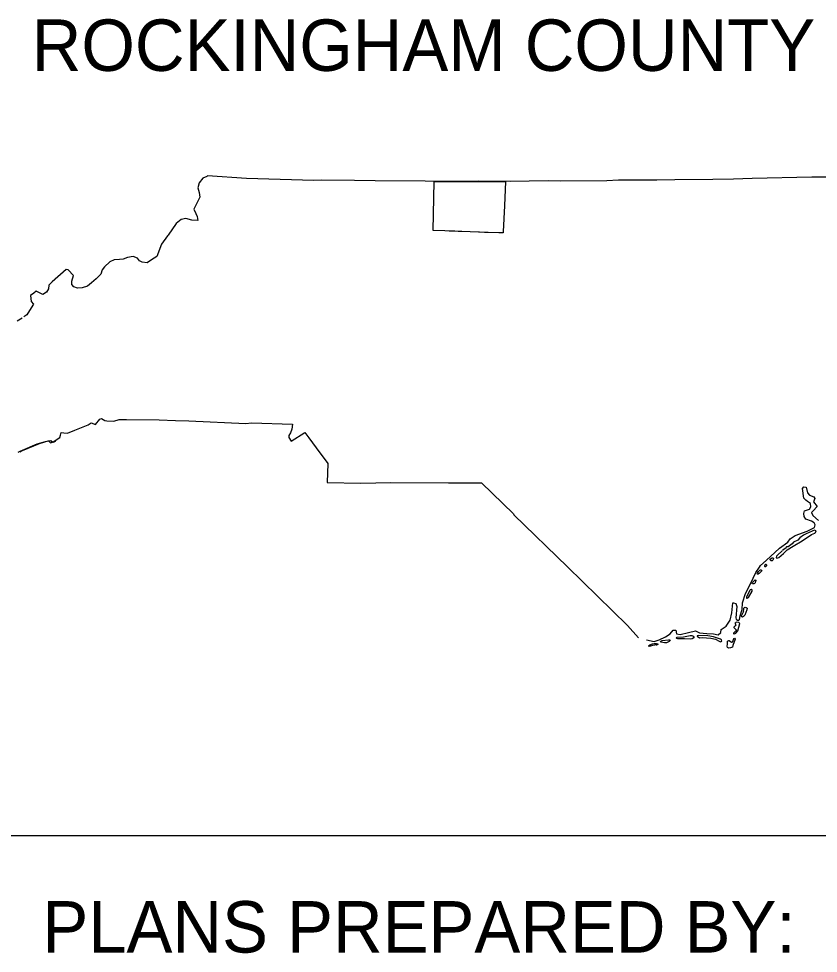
# Model space of a CAD drawing. Extents: x 1677124 to 1678808, y 1331209 to 1332299.
# Drawn here: x 1678714.1 to 1678769.5, y 1332158.3 to 1332223.1 of the extents above; entities that cross this region are included whole.
import ezdxf

# ---------------------------------------------------------------- set-up
doc = ezdxf.new("R2010")
doc.units = 0
for name, color, linetype in [('Old_Level_20', 7, 'Continuous'), ('Prop Shade Light', 7, 'Continuous'), ('Sheet Plan CELL', 7, 'Continuous')]:
    doc.layers.add(name, color=color, linetype=linetype)

msp = doc.modelspace()

# ---------------------------------------------------------------- linework, layer by layer
at = {"layer": 'Old_Level_20'}
for points in [[(1678770.788, 1332212.146), (1678769.029, 1332212.14), (1678764.879, 1332212.049), (1678763.593, 1332212.007), (1678762.155, 1332211.975), (1678759.524, 1332211.947), (1678758.286, 1332211.931), (1678755.619, 1332211.926), (1678754.825, 1332211.875), (1678751.626, 1332211.861), (1678750.747, 1332211.889), (1678748.104, 1332211.831), (1678745.923, 1332211.861), (1678742.851, 1332211.826), (1678742.227, 1332211.863), (1678738.758, 1332211.873), (1678737.321, 1332211.9), (1678735.016, 1332211.922), (1678734.511, 1332211.91), (1678729.832, 1332212.041), (1678727.132, 1332212.221), (1678727.099, 1332212.184), (1678726.804, 1332212.071), (1678726.563, 1332211.732), (1678726.476, 1332211.399), (1678726.557, 1332211.073), (1678726.611, 1332210.75), (1678726.381, 1332210.286), (1678726.194, 1332209.926), (1678726.334, 1332209.62), (1678726.416, 1332209.403), (1678726.477, 1332209.135), (1678726.063, 1332209.161), (1678725.646, 1332209.27), (1678725.317, 1332209.203), (1678724.974, 1332208.932), (1678724.407, 1332208.115), (1678724.359, 1332208.067), (1678723.949, 1332207.49), (1678723.627, 1332206.628), (1678723.25, 1332206.403), (1678722.947, 1332206.209), (1678722.618, 1332206.237), (1678722.422, 1332206.33), (1678722.281, 1332206.526), (1678721.976, 1332206.633), (1678721.593, 1332206.571), (1678721.299, 1332206.444), (1678721.046, 1332206.421), (1678720.671, 1332206.413), (1678720.36, 1332206.261), (1678719.998, 1332205.923), (1678719.846, 1332205.71), (1678719.74, 1332205.423), (1678719.433, 1332205.079), (1678719.094, 1332204.807), (1678718.83, 1332204.58), (1678718.457, 1332204.475), (1678718.135, 1332204.447), (1678717.869, 1332204.533), (1678717.736, 1332204.686), (1678717.737, 1332204.917), (1678717.856, 1332205.312), (1678717.476, 1332205.713), (1678717.34, 1332205.729), (1678716.363, 1332204.892), (1678716.141, 1332204.66), (1678716.108, 1332204.391), (1678715.969, 1332204.162), (1678715.728, 1332204), (1678715.272, 1332204.232), (1678715.104, 1332204.102), (1678714.862, 1332203.926), (1678714.923, 1332203.524), (1678715.081, 1332203.342), (1678714.926, 1332203.088), (1678714.617, 1332202.594), (1678714.42, 1332202.454)], [(1678714.289, 1332202.355), (1678713.951, 1332202.153)], [(1678714.011, 1332193.077), (1678714.156, 1332193.154), (1678715.325, 1332193.643), (1678715.916, 1332193.826), (1678716.122, 1332193.855), (1678716.269, 1332193.73), (1678716.454, 1332193.802), (1678716.908, 1332194.081), (1678716.958, 1332194.262), (1678716.993, 1332194.431), (1678717.193, 1332194.407), (1678717.435, 1332194.391), (1678717.95, 1332194.609), (1678718.864, 1332194.979), (1678719.084, 1332195.112), (1678719.381, 1332194.995), (1678719.672, 1332195.361), (1678719.799, 1332195.399), (1678720.012, 1332195.265), (1678720.173, 1332195.245), (1678720.643, 1332195.213), (1678721.013, 1332195.341), (1678721.527, 1332195.33), (1678723.791, 1332195.311), (1678724.911, 1332195.261), (1678725.846, 1332195.246), (1678729.787, 1332195.073), (1678730.185, 1332195.1), (1678733.04, 1332195.018), (1678732.976, 1332194.665), (1678732.899, 1332194.408), (1678732.766, 1332194.239), (1678732.772, 1332194.091), (1678732.939, 1332193.827), (1678733.882, 1332194.446), (1678734.152, 1332194.06), (1678734.678, 1332193.371), (1678735.485, 1332192.295), (1678735.442, 1332190.966), (1678737.764, 1332190.93), (1678739.853, 1332190.962), (1678743.833, 1332190.948), (1678745.962, 1332190.96), (1678746.123, 1332190.949), (1678748.356, 1332188.803), (1678748.369, 1332188.721), (1678752.098, 1332185.137), (1678756.253, 1332181.064), (1678757.006, 1332180.198)], [(1678716.607, 1332193.814), (1678716.421, 1332193.742), (1678716.272, 1332193.868), (1678716.063, 1332193.839), (1678715.466, 1332193.654), (1678714.286, 1332193.16), (1678714.14, 1332193.083)], [(1678757.568, 1332180.073), (1678758.091, 1332179.96), (1678758.447, 1332180.062), (1678758.878, 1332180.285), (1678759.21, 1332180.485), (1678759.417, 1332180.745), (1678759.593, 1332180.742), (1678759.632, 1332180.495), (1678759.894, 1332180.438), (1678760.472, 1332180.568), (1678760.956, 1332180.702), (1678761.229, 1332180.548), (1678761.736, 1332180.503), (1678762.209, 1332180.49), (1678762.536, 1332180.421), (1678762.712, 1332180.579), (1678762.747, 1332180.774), (1678763.073, 1332181.013), (1678763.364, 1332181.433), (1678763.48, 1332181.937), (1678763.548, 1332182.637), (1678763.588, 1332182.631), (1678763.757, 1332182.588), (1678763.815, 1332182.377), (1678763.746, 1332181.596), (1678763.788, 1332181.494), (1678763.877, 1332181.431), (1678763.965, 1332181.432), (1678764.004, 1332181.489), (1678764.055, 1332181.731), (1678764.186, 1332182.165), (1678764.216, 1332182.644), (1678764.423, 1332183.28), (1678764.759, 1332183.949), (1678765.145, 1332184.743), (1678765.387, 1332185.106), (1678765.474, 1332185.212), (1678765.866, 1332185.575), (1678766.781, 1332186.414), (1678767.348, 1332186.827), (1678767.514, 1332187.068), (1678767.871, 1332187.302), (1678768.692, 1332187.604), (1678769.205, 1332187.864), (1678769.249, 1332188.032), (1678769.18, 1332188.179), (1678768.995, 1332188.293), (1678768.596, 1332188.432), (1678768.494, 1332188.625), (1678768.476, 1332188.831), (1678768.52, 1332188.999), (1678768.859, 1332189.129), (1678768.957, 1332189.288), (1678768.918, 1332189.525), (1678768.724, 1332189.667), (1678768.603, 1332189.756), (1678768.476, 1332189.887), (1678768.364, 1332190.557), (1678768.467, 1332190.674), (1678768.627, 1332190.646), (1678768.72, 1332190.25), (1678768.856, 1332190.091), (1678769.152, 1332189.984), (1678769.226, 1332189.863), (1678769.127, 1332189.623), (1678769.388, 1332189.319), (1678769.111, 1332189.003), (1678769.007, 1332188.886), (1678769.08, 1332188.684), (1678769.481, 1332188.329)], [(1678766.968, 1332186.246), (1678766.647, 1332185.94), (1678766.57, 1332185.856), (1678766.556, 1332185.78), (1678766.592, 1332185.73), (1678766.738, 1332185.767), (1678767.046, 1332186.055), (1678767.308, 1332186.308), (1678767.725, 1332186.565), (1678768.353, 1332186.928), (1678768.995, 1332187.367), (1678769.22, 1332187.458), (1678769.278, 1332187.514), (1678769.332, 1332187.633), (1678769.21, 1332187.68), (1678769.042, 1332187.59), (1678768.626, 1332187.413), (1678768.439, 1332187.33), (1678768.179, 1332187.13), (1678768.04, 1332186.977), (1678767.752, 1332186.838), (1678767.668, 1332186.713), (1678767.381, 1332186.516), (1678767.265, 1332186.504), (1678767.193, 1332186.43), (1678767.171, 1332186.397), (1678766.983, 1332186.255)], [(1678765.8, 1332185.273), (1678765.746, 1332185.213), (1678765.74, 1332185.18), (1678765.755, 1332185.154), (1678765.784, 1332185.148), (1678765.831, 1332185.161), (1678765.887, 1332185.203), (1678765.908, 1332185.229), (1678765.901, 1332185.253), (1678765.854, 1332185.295), (1678765.838, 1332185.301), (1678765.817, 1332185.292), (1678765.804, 1332185.278)], [(1678766.147, 1332185.672), (1678766.268, 1332185.751), (1678766.307, 1332185.756), (1678766.33, 1332185.739), (1678766.357, 1332185.705), (1678766.365, 1332185.673), (1678766.35, 1332185.625), (1678766.314, 1332185.581), (1678766.278, 1332185.554), (1678766.248, 1332185.545), (1678766.214, 1332185.541), (1678766.176, 1332185.576), (1678766.139, 1332185.624), (1678766.133, 1332185.652), (1678766.147, 1332185.672)], [(1678765.262, 1332184.679), (1678765.336, 1332184.803), (1678765.414, 1332184.887), (1678765.462, 1332184.921), (1678765.497, 1332184.924), (1678765.528, 1332184.897), (1678765.546, 1332184.859), (1678765.506, 1332184.815), (1678765.439, 1332184.726), (1678765.381, 1332184.666), (1678765.292, 1332184.618), (1678765.265, 1332184.618), (1678765.248, 1332184.63), (1678765.24, 1332184.645), (1678765.262, 1332184.679)], [(1678764.897, 1332183.98), (1678764.939, 1332184.07), (1678764.991, 1332184.145), (1678765.04, 1332184.185), (1678765.099, 1332184.216), (1678765.133, 1332184.206), (1678765.146, 1332184.176), (1678765.124, 1332184.105), (1678765.086, 1332184.02), (1678765.045, 1332183.981), (1678764.99, 1332183.945), (1678764.918, 1332183.952), (1678764.9, 1332183.96), (1678764.896, 1332183.986)], [(1678764.503, 1332183.034), (1678764.494, 1332182.947), (1678764.509, 1332182.94), (1678764.544, 1332182.945), (1678764.594, 1332182.974), (1678764.624, 1332183.012), (1678764.881, 1332183.443), (1678764.89, 1332183.5), (1678764.879, 1332183.53), (1678764.841, 1332183.556), (1678764.805, 1332183.556), (1678764.751, 1332183.525), (1678764.719, 1332183.485), (1678764.52, 1332183.095), (1678764.502, 1332183.035)], [(1678764.294, 1332182.042), (1678764.3, 1332182.166), (1678764.309, 1332182.257), (1678764.351, 1332182.303), (1678764.411, 1332182.329), (1678764.47, 1332182.312), (1678764.528, 1332182.267), (1678764.527, 1332182.154), (1678764.373, 1332181.789), (1678764.286, 1332181.685), (1678764.208, 1332181.646), (1678764.16, 1332181.668), (1678764.154, 1332181.728), (1678764.216, 1332181.86), (1678764.297, 1332182.05)], [(1678763.759, 1332181.112), (1678763.709, 1332181.03), (1678763.627, 1332180.972), (1678763.614, 1332180.946), (1678763.62, 1332180.914), (1678763.708, 1332180.82), (1678763.755, 1332180.782), (1678763.774, 1332180.767), (1678763.774, 1332180.717), (1678763.596, 1332180.53), (1678763.581, 1332180.504), (1678763.633, 1332180.462), (1678763.67, 1332180.473), (1678763.752, 1332180.525), (1678763.887, 1332180.685), (1678764.034, 1332181.19)], [(1678764.034, 1332181.19), (1678763.96, 1332181.262), (1678763.786, 1332181.288), (1678763.729, 1332181.252), (1678763.689, 1332181.219), (1678763.699, 1332181.183), (1678763.759, 1332181.112)], [(1678758.649, 1332180.016), (1678759.079, 1332180.072), (1678759.164, 1332180.071), (1678759.205, 1332180.056), (1678759.191, 1332179.99), (1678759.131, 1332179.942), (1678758.948, 1332179.869), (1678758.807, 1332179.85), (1678758.585, 1332179.905), (1678758.526, 1332179.934), (1678758.564, 1332179.983), (1678758.659, 1332180.024)], [(1678759.695, 1332180.252), (1678760.116, 1332180.285), (1678760.581, 1332180.364), (1678760.696, 1332180.37), (1678760.793, 1332180.319), (1678760.846, 1332180.254), (1678760.834, 1332180.211), (1678760.724, 1332180.131), (1678760.642, 1332180.108), (1678760.191, 1332180.132), (1678759.865, 1332180.141), (1678759.732, 1332180.142), (1678759.659, 1332180.163), (1678759.631, 1332180.188), (1678759.63, 1332180.206), (1678759.635, 1332180.221), (1678759.694, 1332180.246)], [(1678761.076, 1332180.322), (1678761.239, 1332180.218), (1678761.41, 1332180.225), (1678761.732, 1332180.214), (1678762.025, 1332180.182), (1678762.353, 1332180.111), (1678762.597, 1332179.983), (1678762.698, 1332179.939), (1678762.788, 1332179.98), (1678762.767, 1332180.066), (1678762.696, 1332180.115), (1678762.205, 1332180.28), (1678761.811, 1332180.356), (1678761.166, 1332180.363), (1678761.076, 1332180.352), (1678761.081, 1332180.322)], [(1678763.281, 1332180.019), (1678763.444, 1332179.905), (1678763.484, 1332179.891), (1678763.544, 1332179.962), (1678763.622, 1332180.155), (1678763.667, 1332180.175), (1678763.703, 1332180.115), (1678763.552, 1332179.675), (1678763.519, 1332179.569), (1678763.388, 1332179.507), (1678763.278, 1332179.5), (1678763.176, 1332179.539), (1678763.145, 1332179.64), (1678763.184, 1332179.761), (1678763.171, 1332179.932), (1678763.186, 1332179.968), (1678763.271, 1332180.024), (1678763.296, 1332180.019)], [(1678757.71, 1332179.657), (1678757.798, 1332179.716), (1678757.975, 1332179.789), (1678758.095, 1332179.819), (1678758.172, 1332179.825), (1678758.237, 1332179.817), (1678758.312, 1332179.797), (1678758.346, 1332179.782), (1678758.355, 1332179.763), (1678758.349, 1332179.749), (1678758.264, 1332179.703), (1678758.244, 1332179.71), (1678758.226, 1332179.725), (1678758.147, 1332179.709), (1678757.985, 1332179.678), (1678757.847, 1332179.641), (1678757.766, 1332179.62), (1678757.736, 1332179.617), (1678757.718, 1332179.636), (1678757.71, 1332179.657)]]:
    msp.add_lwpolyline(points, dxfattribs=at)
at = {"layer": 'Prop Shade Light'}
msp.add_lwpolyline([(1678747.639, 1332208.376), (1678747.635, 1332208.274), (1678747.319, 1332208.281), (1678746.601, 1332208.304), (1678746.338, 1332208.307), (1678745.978, 1332208.315), (1678745.915, 1332208.318), (1678744.761, 1332208.358), (1678744.722, 1332208.36), (1678744.683, 1332208.362), (1678744.521, 1332208.369), (1678744.272, 1332208.382), (1678743.88, 1332208.397), (1678743.592, 1332208.406), (1678742.788, 1332208.432), (1678742.851, 1332211.828), (1678743.116, 1332211.828), (1678743.35, 1332211.83), (1678743.597, 1332211.832), (1678743.724, 1332211.833), (1678743.914, 1332211.835), (1678743.972, 1332211.835), (1678744.08, 1332211.836), (1678744.317, 1332211.836), (1678744.38, 1332211.836), (1678744.511, 1332211.836), (1678744.597, 1332211.836), (1678744.715, 1332211.836), (1678744.882, 1332211.836), (1678745.111, 1332211.837), (1678745.251, 1332211.837), (1678745.388, 1332211.837), (1678745.482, 1332211.837), (1678745.515, 1332211.837), (1678745.551, 1332211.837), (1678745.583, 1332211.837), (1678745.606, 1332211.837), (1678745.652, 1332211.837), (1678745.68, 1332211.837), (1678745.707, 1332211.837), (1678745.733, 1332211.837), (1678745.754, 1332211.837), (1678745.765, 1332211.837), (1678745.797, 1332211.837), (1678745.826, 1332211.837), (1678745.853, 1332211.837), (1678745.878, 1332211.837), (1678745.903, 1332211.837), (1678745.941, 1332211.837), (1678745.966, 1332211.837), (1678745.996, 1332211.837), (1678746.03, 1332211.838), (1678746.055, 1332211.837), (1678746.076, 1332211.838), (1678746.099, 1332211.838), (1678746.118, 1332211.838), (1678746.144, 1332211.838), (1678746.179, 1332211.838), (1678746.199, 1332211.838), (1678746.217, 1332211.838), (1678746.233, 1332211.838), (1678746.248, 1332211.838), (1678746.276, 1332211.838), (1678746.309, 1332211.838), (1678746.342, 1332211.838), (1678746.364, 1332211.838), (1678746.386, 1332211.838), (1678746.404, 1332211.839), (1678746.422, 1332211.838), (1678746.459, 1332211.839), (1678746.468, 1332211.838), (1678746.498, 1332211.839), (1678746.526, 1332211.839), (1678746.558, 1332211.839), (1678746.605, 1332211.839), (1678746.649, 1332211.839), (1678746.718, 1332211.839), (1678746.725, 1332211.839), (1678746.744, 1332211.839), (1678746.762, 1332211.839), (1678746.806, 1332211.84), (1678746.832, 1332211.84), (1678746.91, 1332211.84), (1678746.947, 1332211.84), (1678746.958, 1332211.839), (1678746.998, 1332211.839), (1678747.049, 1332211.839), (1678747.785, 1332211.832), (1678747.714, 1332210.152), (1678747.64, 1332208.372)], close=True, dxfattribs=at)
at = {"layer": 'Sheet Plan CELL'}
msp.add_line((1678794.196, 1332166.484), (1678695.171, 1332166.484), dxfattribs=at)

# ---------------------------------------------------------------- texts
for s, p in [('ROCKINGHAM COUNTY', (1678714.956, 1332219.5)), ('PLANS PREPARED BY:', (1678715.695, 1332158.393))]:
    msp.add_text(s, height=3.56495, rotation=0, dxfattribs=at).set_placement(p)

doc.saveas('drawing.dxf')
